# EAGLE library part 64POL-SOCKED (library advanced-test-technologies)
QFP SOCKED 64 pol. Source: WELLS CTI 7014-064-6-08 TQFP 64 - Drawing.pdf
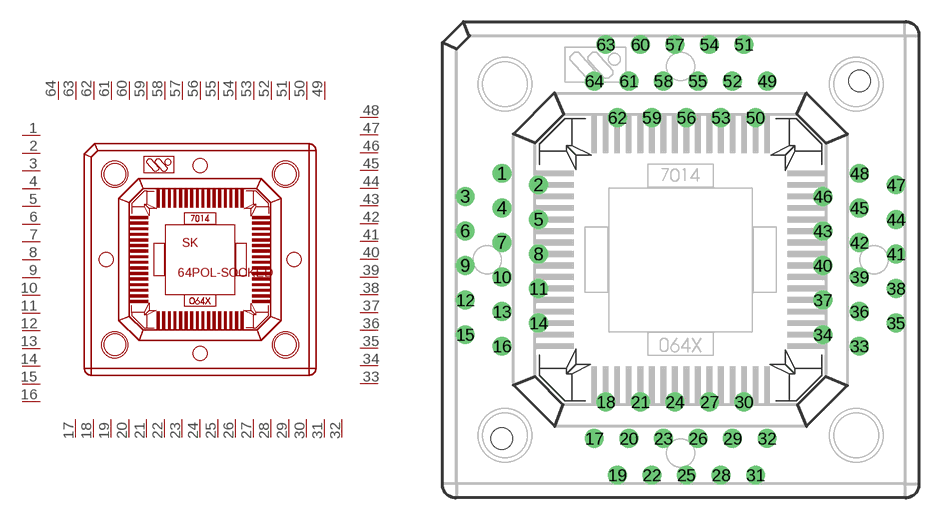
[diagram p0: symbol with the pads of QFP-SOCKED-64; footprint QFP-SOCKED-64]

Designator prefix SK

## 64POL-SOCKED  [QFP-SOCKED-64]
1  1  pas
2  2  pas
3  3  pas
4  4  pas
5  5  pas
6  6  pas
7  7  pas
8  8  pas
9  9  pas
10  10  pas
11  11  pas
12  12  pas
13  13  pas
14  14  pas
15  15  pas
16  16  pas
17  17  pas
18  18  pas
19  19  pas
20  20  pas
21  21  pas
22  22  pas
23  23  pas
24  24  pas
25  25  pas
26  26  pas
27  27  pas
28  28  pas
29  29  pas
30  30  pas
31  31  pas
32  32  pas
33  33  pas
34  34  pas
35  35  pas
36  36  pas
37  37  pas
38  38  pas
39  39  pas
40  40  pas
41  41  pas
42  42  pas
43  43  pas
44  44  pas
45  45  pas
46  46  pas
47  47  pas
48  48  pas
49  49  pas
50  50  pas
51  51  pas
52  52  pas
53  53  pas
54  54  pas
55  55  pas
56  56  pas
57  57  pas
58  58  pas
59  59  pas
60  60  pas
61  61  pas
62  62  pas
63  63  pas
64  64  pas

## Footprint QFP-SOCKED-64 (pad centres in mm)
QFP SOCKED 64 pol. Source: WELLS CTI 7014-064-6-08 TQFP 64 - Drawing.pdf
drill 0.8 pad 1.2 round: 1 -12.41,6; 2 -9.87,5.2; 3 -14.95,4.4; 4 -12.41,3.6; 5 -9.87,2.8; 6 -14.95,2; 7 -12.41,1.2; 8 -9.87,0.4; 9 -14.95,-0.4; 10 -12.41,-1.2; 11 -9.87,-2; 12 -14.95,-2.8; 13 -12.41,-3.6; 14 -9.87,-4.4; 15 -14.95,-5.2; 16 -12.41,-6; 17 -6,-12.41; 18 -5.2,-9.87; 19 -4.4,-14.95; 20 -3.6,-12.41; 21 -2.8,-9.87; 22 -2,-14.95; 23 -1.2,-12.41; 24 -0.4,-9.87; 25 0.4,-14.95; 26 1.2,-12.41; 27 2,-9.87; 28 2.8,-14.95; 29 3.6,-12.41; 30 4.4,-9.87; 31 5.2,-14.95; 32 6,-12.41; 33 12.41,-6; 34 9.87,-5.2; 35 14.95,-4.4; 36 12.41,-3.6; 37 9.87,-2.8; 38 14.95,-2; 39 12.41,-1.2; 40 9.87,-0.4; 41 14.95,0.4; 42 12.41,1.2; 43 9.87,2; 44 14.95,2.8; 45 12.41,3.6; 46 9.87,4.4; 47 14.95,5.2; 48 12.41,6; 49 6,12.41; 50 5.2,9.87; 51 4.4,14.95; 52 3.6,12.41; 53 2.8,9.87; 54 2,14.95; 55 1.2,12.41; 56 0.4,9.87; 57 -0.4,14.95; 58 -1.2,12.41; 59 -2,9.87; 60 -2.8,14.95; 61 -3.6,12.41; 62 -4.4,9.87; 63 -5.2,14.95; 64 -6,12.41
hole 1.5 at -12.41,-12.41
hole 1.5 at 12.41,12.41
